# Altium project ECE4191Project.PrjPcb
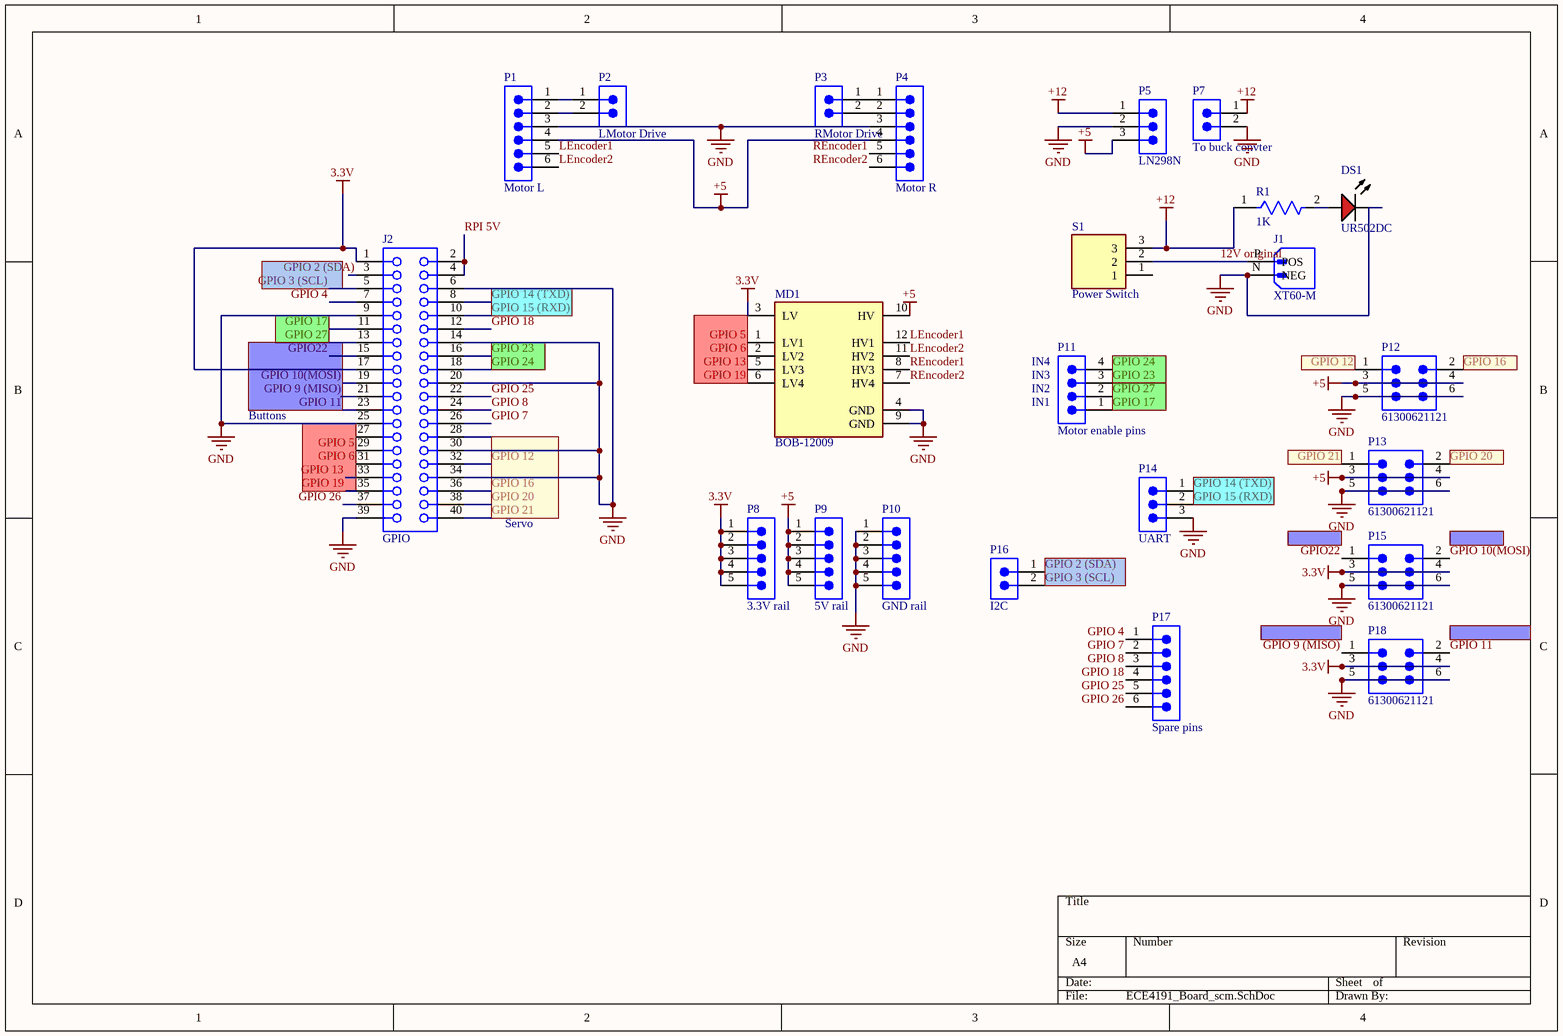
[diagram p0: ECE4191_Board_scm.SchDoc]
1 sheet, 23 parts. Net scope: global (net labels, ports and power ports of the same name join across sheets).
Board file: ECE4191_Board_pcb.PcbDoc

## Sheet ECE4191_Board_scm.SchDoc
size A4; SheetNumber: 1; SheetTotal: 1

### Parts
DS1  UR502DC  [CGX-UR502DC]
J1  XT60-M  [AMASS_XT60-M]
J2  GPIO  [61304021821]
MD1  BOB-12009  [FP-BOB-12009-MFG]
P1  Motor L  [61300611121]
P2  LMotor Drive  [61300211121]
P3  RMotor Drive  [61300211121]
P4  Motor R  [61300611121]
P5  LN298N  [61300311121]
P7  To buck convter  [61300211121]
P8  3.3V rail  [61300511121]
P9  5V rail  [61300511121]
P10  GND rail  [61300511121]
P11  Motor enable pins  [61300411121]
P12  61300621121  [61300621121]
P13  61300621121  [61300621121]
P14  UART  [61300311121]
P15  61300621121  [61300621121]
P16  I2C  [61300211121]
P17  Spare pins  [61300611121]
P18  61300621121  [61300621121]
R1  1K  [FP-MRS25-MFG]
S1  Power Switch  [1MS1T1B1M1QES-1]

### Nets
3.3V: J2.1 J2.17 MD1.3(LV) P8.1 P8.2 P8.3 P8.4 P8.5 P15.3 P15.4 P18.3 P18.4
+5: MD1.10(HV) P1.4 P4.4 P5.3 P9.1 P9.2 P9.3 P9.4 P9.5 P12.3 P12.4 P13.3 P13.4
+12: P5.1 P7.1 R1.1 S1.3
GND: DS1.2(K) J1.N(NEG) J2.6 J2.9 J2.14 J2.20 J2.25 J2.30 J2.34 J2.39 MD1.4(GND) MD1.9(GND) P1.3 P4.3 P5.2 P7.2 P10.1 P10.2 P10.3 P10.4 P10.5 P12.5 P12.6 P13.5 P13.6 P14.3 P15.5 P15.6 P18.5 P18.6
12V original: J1.P(POS) S1.2
GPIO22: J2.15 P15.1
GPIO 2 (SDA): J2.3 P16.1
GPIO 3 (SCL): J2.5 P16.2
GPIO 4: J2.7 P17.1
GPIO 5: J2.29 MD1.1(LV1)
GPIO 6: J2.31 MD1.2(LV2)
GPIO 7: J2.26 P17.2
GPIO 8: J2.24 P17.3
GPIO 9 (MISO): J2.21 P18.1
GPIO 10(MOSI): J2.19 P15.2
GPIO 11: J2.23 P18.2
GPIO 12: J2.32 P12.1
GPIO 13: J2.33 MD1.5(LV3)
GPIO 14 (TXD): J2.8 P14.1
GPIO 15 (RXD): J2.10 P14.2
GPIO 16: J2.36 P12.2
GPIO 17: J2.11 P11.1
GPIO 18: J2.12 P17.4
GPIO 19: J2.35 MD1.6(LV4)
GPIO 20: J2.38 P13.2
GPIO 21: J2.40 P13.1
GPIO 23: J2.16 P11.3
GPIO 24: J2.18 P11.4
GPIO 25: J2.22 P17.5
GPIO 26: J2.37 P17.6
GPIO 27: J2.13 P11.2
LEncoder1: MD1.12(HV1) P1.5
LEncoder2: MD1.11(HV2) P1.6
REncoder1: MD1.8(HV3) P4.5
REncoder2: MD1.7(HV4) P4.6
RPI 5V: J2.2 J2.4
NetDS1_1: DS1.1(A) R1.2
NetP1_1: P1.1 P2.1
NetP1_2: P1.2 P2.2
NetP3_1: P3.1 P4.1
NetP3_2: P3.2 P4.2

Not connected (* = marked no-connect by the designer): J2 27 28; S1 1

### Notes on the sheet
- (near P11) IN3
- (near P11) IN4
- Buttons
- (near P11) IN1
- (near P11) IN2
- Servo

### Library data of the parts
DS1 = CMP-007-00009-1: Red LED, 80 mW, 30 mA, -25 to 85 degC, 2-Pin THD; Manufacturer: Shenzhen CGX; Power: 80mW
J1 = XT60-M: Plug; DC supply; XT60; male; PIN: 2; for cable; soldered; 30A; 500V; MF: AMASS
J2 = CMP-1502-01370-3: NexarPartId: 61924769; Gender: Female; Contact Resistance: 20mΩ; Current Rating: 3A; Operating Supply Voltage: 250V
MD1 = CMP-157458-000001-1: LOGIC LEVEL CONVERTER - BI-DIREC; Logic Function: Translator
P1 P4 P17 = CMP-1502-01070-3: NexarPartId: 20084590; Current Rating: 3A; Pitch: 2.54mm; Gender: Male; Operating Supply Voltage: 250V; Connector Type: Male Pin; Number of Positions: 6; Contact Resistance: 20mΩ
P2 P3 P7 P16 = CMP-1712-00002-6: NexarPartId: 20081794; Number of Contacts: 2; Pitch: 2.54mm; Connector Type: Male Pin; Voltage Rating: 250V; Current Rating: 3A; Gender: Male; Contact Resistance: 20mΩ
P5 P14 = CMP-1502-01062-3: NexarPartId: 32855521; Current Rating: 3A; Voltage Rating: 250V; Number of Positions: 3; Pitch: 2.54mm; Contact Resistance: 20mΩ; Connector Type: Male Pin; Gender: Male
P8-P10 = CMP-1502-01068-3: NexarPartId: 32855526; Connector Type: Male Pin; Gender: Male; Contact Resistance: 20mΩ; Pitch: 2.54mm; Operating Supply Voltage: 250V; Current Rating: 3A; Number of Contacts: 5
P11 = CMP-1502-01064-3: NexarPartId: 32855522; Operating Supply Voltage: 250V; Pitch: 2.54mm; Contact Resistance: 20mΩ; Number of Positions: 4; Current Rating: 3A; Connector Type: Male Pin; Gender: Male
P12 P13 P15 P18 = CMP-1502-01072-3: NexarPartId: 32855529; Row Spacing: 2.54mm; Current Rating: 3A; Voltage Rating: 250V; Contact Resistance: 20mΩ; Connector Type: Male Pin; Number of Positions: 6; Gender: Male
R1 = CMP-00030-42632392-1: 1K resistor; Power Rating: 600mW; Voltage Rating (DC): 350V; Lead Length: 26mm; Resistance: 10kΩ; Tolerance: 1%; Temperature Coefficient: 50ppm/°C
S1 = 1MS1T1B1M1QES-1: Switch; Manufacturer_Name: RS Pro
